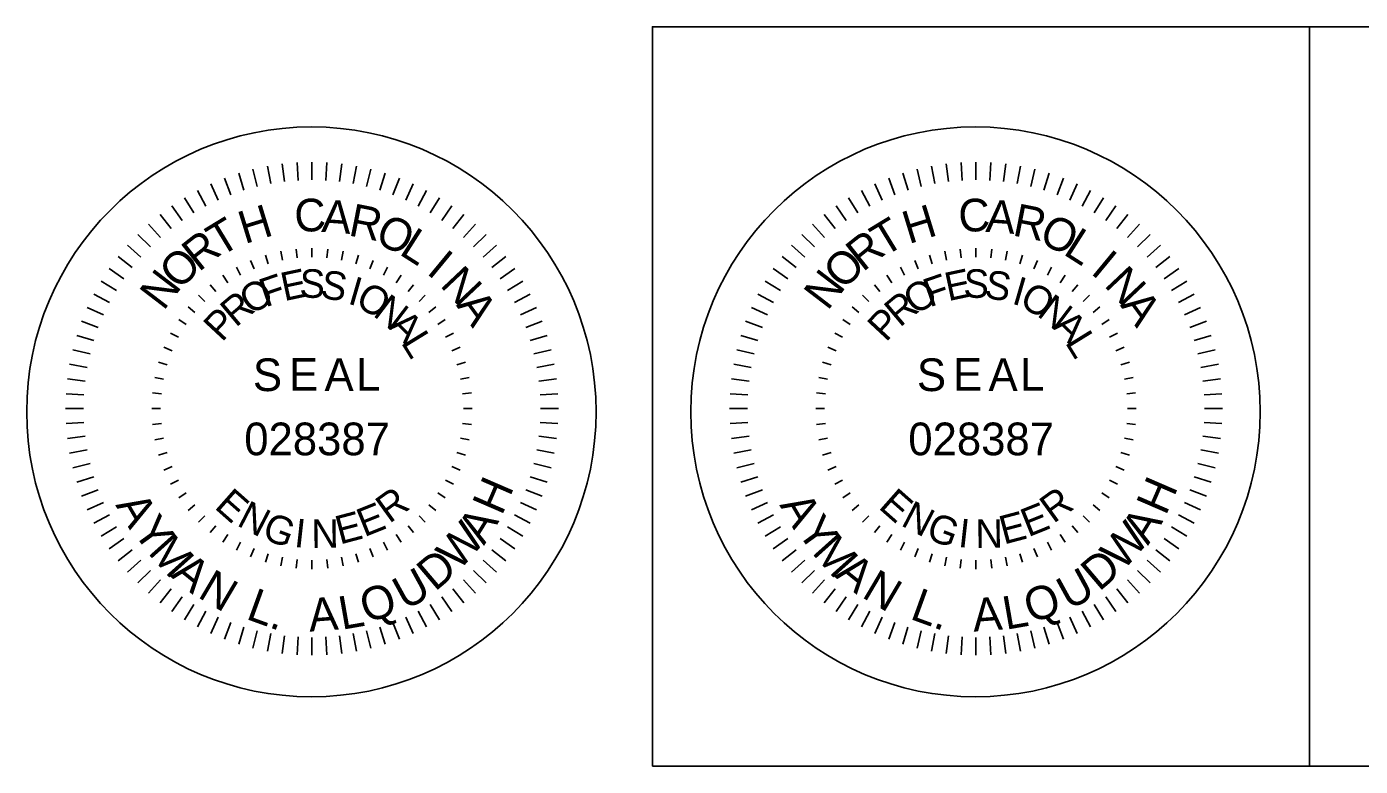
# Model space of a CAD drawing. Extents: x 1882804 to 1884487, y 844572 to 845443.
# Drawn here: x 1884074.3 to 1884277.3, y 845330.9 to 845443.4 of the extents above; entities that cross this region are included whole.
import ezdxf

# ---------------------------------------------------------------- set-up
doc = ezdxf.new("R2010")
doc.units = 0
doc.layers.add('Scratch_Level_1', color=7, linetype='Continuous')
doc.layers.add('Sheet Title CELL', color=7, linetype='Continuous')

msp = doc.modelspace()

# ---------------------------------------------------------------- linework, layer by layer
at = {"layer": 'Scratch_Level_1'}
for points in [[(1884169.55, 845330.93), (1884269.6, 845330.93), (1884269.6, 845443.43), (1884169.55, 845443.43)], [(1884269.6, 845330.93), (1884369.6, 845330.93), (1884369.6, 845443.43), (1884269.6, 845443.43)]]:
    msp.add_lwpolyline(points, close=True, dxfattribs=at)
for centre in [(1884117.65, 845384.84), (1884117.65, 845384.84), (1884218.73, 845384.84), (1884218.73, 845384.84)]:
    msp.add_circle(centre, 43.34, dxfattribs=at)
at = {"layer": 'Sheet Title CELL'}
for p, q in [((1884111.47, 845419.55), (1884110.98, 845422.21)), ((1884113.54, 845419.86), (1884113.22, 845422.55)), ((1884115.64, 845420.05), (1884115.47, 845422.76)), ((1884117.74, 845420.12), (1884117.74, 845422.83)), ((1884119.84, 845420.05), (1884120, 845422.76)), ((1884121.93, 845419.86), (1884122.26, 845422.55)), ((1884124.01, 845419.55), (1884124.5, 845422.21)), ((1884212.54, 845419.55), (1884212.05, 845422.21)), ((1884214.62, 845419.86), (1884214.29, 845422.55)), ((1884216.71, 845420.05), (1884216.55, 845422.76)), ((1884218.81, 845420.12), (1884218.81, 845422.83)), ((1884220.92, 845420.05), (1884221.08, 845422.76)), ((1884223.01, 845419.86), (1884223.34, 845422.55)), ((1884225.08, 845419.55), (1884225.57, 845422.21)), ((1884105.4, 845417.85), (1884104.44, 845420.39)), ((1884107.39, 845418.54), (1884106.58, 845421.13)), ((1884109.41, 845419.1), (1884108.76, 845421.74)), ((1884126.06, 845419.1), (1884126.71, 845421.74)), ((1884128.09, 845418.54), (1884128.89, 845421.13)), ((1884130.07, 845417.85), (1884131.04, 845420.39)), ((1884206.48, 845417.85), (1884205.52, 845420.39)), ((1884208.47, 845418.54), (1884207.66, 845421.13)), ((1884210.49, 845419.1), (1884209.84, 845421.74)), ((1884227.14, 845419.1), (1884227.79, 845421.74)), ((1884229.16, 845418.54), (1884229.97, 845421.13)), ((1884231.15, 845417.85), (1884232.11, 845420.39)), ((1884101.57, 845416.13), (1884100.31, 845418.53)), ((1884103.46, 845417.05), (1884102.35, 845419.52)), ((1884132.02, 845417.05), (1884133.13, 845419.52)), ((1884133.9, 845416.13), (1884135.16, 845418.53)), ((1884202.65, 845416.13), (1884201.39, 845418.53)), ((1884204.53, 845417.05), (1884203.42, 845419.52)), ((1884233.09, 845417.05), (1884234.2, 845419.52)), ((1884234.98, 845416.13), (1884236.24, 845418.53)), ((1884097.98, 845413.96), (1884096.43, 845416.19)), ((1884099.74, 845415.1), (1884098.34, 845417.42)), ((1884135.73, 845415.1), (1884137.14, 845417.42)), ((1884137.5, 845413.96), (1884139.04, 845416.19)), ((1884199.05, 845413.96), (1884197.51, 845416.19)), ((1884200.82, 845415.1), (1884199.41, 845417.42)), ((1884236.81, 845415.1), (1884238.21, 845417.42)), ((1884238.58, 845413.96), (1884240.12, 845416.19)), ((1884096.28, 845412.71), (1884094.61, 845414.84)), ((1884139.19, 845412.71), (1884140.86, 845414.84)), ((1884197.36, 845412.71), (1884195.69, 845414.84)), ((1884240.27, 845412.71), (1884241.94, 845414.84)), ((1884094.67, 845411.37), (1884092.87, 845413.4)), ((1884140.81, 845411.37), (1884142.61, 845413.4)), ((1884195.74, 845411.37), (1884193.95, 845413.4)), ((1884241.88, 845411.37), (1884243.68, 845413.4)), ((1884091.7, 845408.39), (1884089.67, 845410.19)), ((1884093.14, 845409.93), (1884091.22, 845411.84)), ((1884142.34, 845409.93), (1884144.25, 845411.84)), ((1884143.78, 845408.39), (1884145.81, 845410.19)), ((1884192.77, 845408.39), (1884190.75, 845410.19)), ((1884194.21, 845409.93), (1884192.3, 845411.84)), ((1884243.41, 845409.93), (1884245.33, 845411.84)), ((1884244.85, 845408.39), (1884246.88, 845410.19)), ((1884090.35, 845406.78), (1884088.22, 845408.45)), ((1884108.92, 845406.61), (1884108.4, 845407.87)), ((1884111.05, 845407.38), (1884110.65, 845408.67)), ((1884113.24, 845407.93), (1884112.98, 845409.26)), ((1884115.48, 845408.26), (1884115.35, 845409.61)), ((1884117.74, 845408.37), (1884117.74, 845409.72)), ((1884120, 845408.26), (1884120.13, 845409.61)), ((1884122.23, 845407.93), (1884122.5, 845409.26)), ((1884124.43, 845407.38), (1884124.82, 845408.67)), ((1884126.56, 845406.61), (1884127.07, 845407.87)), ((1884145.12, 845406.78), (1884147.26, 845408.45)), ((1884191.43, 845406.78), (1884189.29, 845408.45)), ((1884210, 845406.61), (1884209.48, 845407.87)), ((1884212.13, 845407.38), (1884211.73, 845408.67)), ((1884214.32, 845407.93), (1884214.05, 845409.26)), ((1884216.55, 845408.26), (1884216.42, 845409.61)), ((1884218.81, 845408.37), (1884218.81, 845409.72)), ((1884221.07, 845408.26), (1884221.2, 845409.61)), ((1884223.31, 845407.93), (1884223.58, 845409.26)), ((1884225.5, 845407.38), (1884225.9, 845408.67)), ((1884227.63, 845406.61), (1884228.15, 845407.87)), ((1884246.2, 845406.78), (1884248.34, 845408.45)), ((1884089.11, 845405.09), (1884086.88, 845406.63)), ((1884106.88, 845405.65), (1884106.24, 845406.84)), ((1884128.6, 845405.65), (1884129.24, 845406.84)), ((1884146.37, 845405.09), (1884148.6, 845406.63)), ((1884190.18, 845405.09), (1884187.95, 845406.63)), ((1884207.95, 845405.65), (1884207.31, 845406.84)), ((1884229.68, 845405.65), (1884230.31, 845406.84)), ((1884247.45, 845405.09), (1884249.68, 845406.63)), ((1884087.97, 845403.32), (1884085.64, 845404.73)), ((1884103.12, 845403.14), (1884102.26, 845404.18)), ((1884104.94, 845404.49), (1884104.18, 845405.61)), ((1884130.54, 845404.49), (1884131.29, 845405.61)), ((1884132.36, 845403.14), (1884133.21, 845404.18)), ((1884147.51, 845403.32), (1884149.83, 845404.73)), ((1884189.04, 845403.32), (1884186.72, 845404.73)), ((1884204.2, 845403.14), (1884203.34, 845404.18)), ((1884206.01, 845404.49), (1884205.26, 845405.61)), ((1884231.62, 845404.49), (1884232.37, 845405.61)), ((1884233.43, 845403.14), (1884234.29, 845404.18)), ((1884248.59, 845403.32), (1884250.91, 845404.73)), ((1884086.93, 845401.49), (1884084.53, 845402.75)), ((1884101.44, 845401.62), (1884100.49, 845402.58)), ((1884134.03, 845401.62), (1884134.99, 845402.58)), ((1884148.54, 845401.49), (1884150.94, 845402.75)), ((1884188.01, 845401.49), (1884185.61, 845402.75)), ((1884202.52, 845401.62), (1884201.56, 845402.58)), ((1884235.11, 845401.62), (1884236.07, 845402.58)), ((1884249.62, 845401.49), (1884252.02, 845402.75)), ((1884086.01, 845399.6), (1884083.54, 845400.72)), ((1884099.93, 845399.94), (1884098.88, 845400.8)), ((1884135.55, 845399.94), (1884136.6, 845400.8)), ((1884149.46, 845399.6), (1884151.93, 845400.72)), ((1884187.09, 845399.6), (1884184.62, 845400.72)), ((1884201, 845399.94), (1884199.95, 845400.8)), ((1884236.63, 845399.94), (1884237.67, 845400.8)), ((1884250.54, 845399.6), (1884253.01, 845400.72)), ((1884085.21, 845397.66), (1884082.67, 845398.62)), ((1884098.58, 845398.13), (1884097.45, 845398.88)), ((1884136.9, 845398.13), (1884138.02, 845398.88)), ((1884150.27, 845397.66), (1884152.8, 845398.62)), ((1884186.29, 845397.66), (1884183.75, 845398.62)), ((1884199.65, 845398.13), (1884198.53, 845398.88)), ((1884237.97, 845398.13), (1884239.1, 845398.88)), ((1884251.34, 845397.66), (1884253.88, 845398.62)), ((1884084.52, 845395.68), (1884081.94, 845396.48)), ((1884097.41, 845396.19), (1884096.22, 845396.83)), ((1884138.06, 845396.19), (1884139.26, 845396.83)), ((1884150.95, 845395.68), (1884153.54, 845396.48)), ((1884185.6, 845395.68), (1884183.01, 845396.48)), ((1884198.49, 845396.19), (1884197.3, 845396.83)), ((1884239.14, 845396.19), (1884240.33, 845396.83)), ((1884252.03, 845395.68), (1884254.62, 845396.48)), ((1884083.96, 845393.65), (1884081.33, 845394.3)), ((1884096.45, 845394.14), (1884095.2, 845394.66)), ((1884139.03, 845394.14), (1884140.28, 845394.66)), ((1884151.52, 845393.65), (1884154.15, 845394.3)), ((1884185.04, 845393.65), (1884182.4, 845394.3)), ((1884197.53, 845394.14), (1884196.27, 845394.66)), ((1884240.1, 845394.14), (1884241.36, 845394.66)), ((1884252.59, 845393.65), (1884255.23, 845394.3)), ((1884083.52, 845391.6), (1884080.85, 845392.08)), ((1884095.69, 845392.01), (1884094.39, 845392.41)), ((1884139.79, 845392.01), (1884141.09, 845392.41)), ((1884151.96, 845391.6), (1884154.62, 845392.08)), ((1884184.59, 845391.6), (1884181.93, 845392.08)), ((1884196.76, 845392.01), (1884195.47, 845392.41)), ((1884240.86, 845392.01), (1884242.16, 845392.41)), ((1884253.03, 845391.6), (1884255.7, 845392.08)), ((1884083.2, 845389.52), (1884080.51, 845389.85)), ((1884095.14, 845389.82), (1884093.81, 845390.08)), ((1884140.34, 845389.82), (1884141.67, 845390.08)), ((1884152.27, 845389.52), (1884154.96, 845389.85)), ((1884184.28, 845389.52), (1884181.59, 845389.85)), ((1884196.21, 845389.82), (1884194.89, 845390.08)), ((1884241.41, 845389.82), (1884242.74, 845390.08)), ((1884253.35, 845389.52), (1884256.04, 845389.85)), ((1884083.01, 845387.42), (1884080.31, 845387.59)), ((1884094.81, 845387.58), (1884093.46, 845387.72)), ((1884140.67, 845387.58), (1884142.02, 845387.72)), ((1884152.46, 845387.42), (1884155.17, 845387.59)), ((1884184.09, 845387.42), (1884181.38, 845387.59)), ((1884195.88, 845387.58), (1884194.53, 845387.72)), ((1884241.75, 845387.58), (1884243.09, 845387.72)), ((1884253.54, 845387.42), (1884256.25, 845387.59)), ((1884082.95, 845385.33), (1884080.24, 845385.33)), ((1884094.69, 845385.33), (1884093.34, 845385.33)), ((1884140.78, 845385.33), (1884142.13, 845385.33)), ((1884152.53, 845385.33), (1884155.24, 845385.33)), ((1884184.02, 845385.33), (1884181.31, 845385.33)), ((1884195.77, 845385.33), (1884194.42, 845385.33)), ((1884241.86, 845385.33), (1884243.21, 845385.33)), ((1884253.6, 845385.33), (1884256.31, 845385.33)), ((1884083.01, 845383.22), (1884080.31, 845383.06)), ((1884094.81, 845383.07), (1884093.46, 845382.94)), ((1884140.67, 845383.07), (1884142.02, 845382.94)), ((1884152.46, 845383.22), (1884155.17, 845383.06)), ((1884184.09, 845383.22), (1884181.38, 845383.06)), ((1884195.88, 845383.07), (1884194.53, 845382.94)), ((1884241.75, 845383.07), (1884243.09, 845382.94)), ((1884253.54, 845383.22), (1884256.25, 845383.06)), ((1884083.2, 845381.13), (1884080.51, 845380.81)), ((1884095.14, 845380.83), (1884093.81, 845380.57)), ((1884140.34, 845380.83), (1884141.67, 845380.57)), ((1884152.27, 845381.13), (1884154.96, 845380.81)), ((1884184.28, 845381.13), (1884181.59, 845380.81)), ((1884196.21, 845380.83), (1884194.88, 845380.57)), ((1884241.41, 845380.83), (1884242.74, 845380.57)), ((1884253.35, 845381.13), (1884256.04, 845380.81)), ((1884083.52, 845379.05), (1884080.85, 845378.57)), ((1884095.69, 845378.64), (1884094.39, 845378.24)), ((1884139.79, 845378.64), (1884141.09, 845378.24)), ((1884151.96, 845379.05), (1884154.62, 845378.57)), ((1884184.59, 845379.05), (1884181.93, 845378.57)), ((1884196.77, 845378.64), (1884195.47, 845378.24)), ((1884240.86, 845378.64), (1884242.16, 845378.24)), ((1884253.03, 845379.05), (1884255.7, 845378.57)), ((1884083.96, 845377), (1884081.33, 845376.35)), ((1884096.45, 845376.51), (1884095.2, 845375.99)), ((1884139.03, 845376.51), (1884140.28, 845375.99)), ((1884151.52, 845377), (1884154.15, 845376.35)), ((1884185.04, 845377), (1884182.4, 845376.35)), ((1884197.53, 845376.51), (1884196.27, 845375.99)), ((1884240.1, 845376.51), (1884241.36, 845375.99)), ((1884252.59, 845377), (1884255.23, 845376.35)), ((1884084.52, 845374.98), (1884081.94, 845374.17)), ((1884097.42, 845374.46), (1884096.22, 845373.82)), ((1884138.06, 845374.46), (1884139.26, 845373.82)), ((1884150.95, 845374.97), (1884153.54, 845374.17)), ((1884185.6, 845374.98), (1884183.01, 845374.17)), ((1884198.49, 845374.46), (1884197.3, 845373.82)), ((1884239.14, 845374.46), (1884240.33, 845373.82)), ((1884252.03, 845374.97), (1884254.61, 845374.17)), ((1884085.21, 845372.99), (1884082.67, 845372.03)), ((1884098.58, 845372.52), (1884097.45, 845371.77)), ((1884136.9, 845372.52), (1884138.02, 845371.77)), ((1884150.27, 845372.99), (1884152.8, 845372.03)), ((1884186.29, 845372.99), (1884183.75, 845372.03)), ((1884199.66, 845372.52), (1884198.53, 845371.77)), ((1884237.97, 845372.52), (1884239.1, 845371.77)), ((1884251.34, 845372.99), (1884253.88, 845372.03)), ((1884086.01, 845371.05), (1884083.54, 845369.93)), ((1884099.93, 845370.71), (1884098.88, 845369.85)), ((1884135.55, 845370.71), (1884136.6, 845369.85)), ((1884149.46, 845371.05), (1884151.93, 845369.93)), ((1884187.09, 845371.05), (1884184.62, 845369.93)), ((1884201, 845370.71), (1884199.95, 845369.85)), ((1884236.63, 845370.71), (1884237.67, 845369.85)), ((1884250.54, 845371.05), (1884253.01, 845369.93)), ((1884086.93, 845369.16), (1884084.53, 845367.9)), ((1884087.97, 845367.33), (1884085.64, 845365.92)), ((1884101.44, 845369.03), (1884100.49, 845368.07)), ((1884103.12, 845367.51), (1884102.26, 845366.47)), ((1884132.36, 845367.51), (1884133.21, 845366.47)), ((1884134.03, 845369.03), (1884134.99, 845368.07)), ((1884147.51, 845367.33), (1884149.83, 845365.92)), ((1884148.54, 845369.16), (1884150.94, 845367.9)), ((1884188.01, 845369.16), (1884185.61, 845367.9)), ((1884189.04, 845367.33), (1884186.72, 845365.92)), ((1884202.52, 845369.03), (1884201.56, 845368.07)), ((1884204.19, 845367.51), (1884203.34, 845366.47)), ((1884233.43, 845367.51), (1884234.29, 845366.47)), ((1884235.11, 845369.03), (1884236.07, 845368.07)), ((1884248.59, 845367.33), (1884250.91, 845365.92)), ((1884249.62, 845369.16), (1884252.02, 845367.9)), ((1884089.11, 845365.56), (1884086.88, 845364.02)), ((1884104.94, 845366.17), (1884104.18, 845365.04)), ((1884130.54, 845366.17), (1884131.29, 845365.04)), ((1884146.37, 845365.56), (1884148.6, 845364.02)), ((1884190.18, 845365.56), (1884187.95, 845364.02)), ((1884206.01, 845366.17), (1884205.26, 845365.04)), ((1884231.61, 845366.17), (1884232.37, 845365.04)), ((1884247.45, 845365.56), (1884249.68, 845364.02)), ((1884090.35, 845363.87), (1884088.22, 845362.2)), ((1884106.88, 845365), (1884106.24, 845363.81)), ((1884108.92, 845364.04), (1884108.4, 845362.79)), ((1884111.05, 845363.27), (1884110.65, 845361.98)), ((1884124.43, 845363.27), (1884124.82, 845361.98)), ((1884126.56, 845364.04), (1884127.07, 845362.79)), ((1884128.6, 845365), (1884129.24, 845363.81)), ((1884145.12, 845363.87), (1884147.26, 845362.2)), ((1884191.43, 845363.87), (1884189.29, 845362.2)), ((1884207.95, 845365), (1884207.31, 845363.81)), ((1884210, 845364.04), (1884209.48, 845362.79)), ((1884212.13, 845363.27), (1884211.73, 845361.98)), ((1884225.5, 845363.27), (1884225.9, 845361.98)), ((1884227.63, 845364.04), (1884228.15, 845362.79)), ((1884229.68, 845365), (1884230.31, 845363.81)), ((1884246.2, 845363.87), (1884248.34, 845362.2)), ((1884091.7, 845362.26), (1884089.67, 845360.46)), ((1884113.24, 845362.73), (1884112.98, 845361.4)), ((1884115.48, 845362.39), (1884115.35, 845361.05)), ((1884117.74, 845362.28), (1884117.74, 845360.93)), ((1884120, 845362.39), (1884120.13, 845361.05)), ((1884122.23, 845362.73), (1884122.5, 845361.4)), ((1884143.78, 845362.26), (1884145.81, 845360.46)), ((1884192.77, 845362.26), (1884190.75, 845360.46)), ((1884214.32, 845362.73), (1884214.05, 845361.4)), ((1884216.55, 845362.39), (1884216.42, 845361.05)), ((1884218.81, 845362.28), (1884218.81, 845360.93)), ((1884221.07, 845362.39), (1884221.2, 845361.05)), ((1884223.31, 845362.73), (1884223.58, 845361.4)), ((1884244.85, 845362.26), (1884246.88, 845360.46)), ((1884093.14, 845360.73), (1884091.22, 845358.81)), ((1884094.67, 845359.29), (1884092.87, 845357.26)), ((1884140.81, 845359.29), (1884142.61, 845357.26)), ((1884142.34, 845360.73), (1884144.25, 845358.81)), ((1884194.21, 845360.73), (1884192.3, 845358.81)), ((1884195.74, 845359.29), (1884193.95, 845357.26)), ((1884241.88, 845359.29), (1884243.68, 845357.26)), ((1884243.41, 845360.73), (1884245.33, 845358.81)), ((1884096.28, 845357.94), (1884094.61, 845355.81)), ((1884139.19, 845357.94), (1884140.87, 845355.81)), ((1884197.36, 845357.94), (1884195.69, 845355.81)), ((1884240.27, 845357.94), (1884241.94, 845355.81)), ((1884097.98, 845356.69), (1884096.43, 845354.46)), ((1884099.74, 845355.55), (1884098.34, 845353.23)), ((1884135.73, 845355.55), (1884137.14, 845353.23)), ((1884137.5, 845356.69), (1884139.04, 845354.46)), ((1884199.05, 845356.69), (1884197.51, 845354.46)), ((1884200.82, 845355.55), (1884199.41, 845353.23)), ((1884236.81, 845355.55), (1884238.21, 845353.23)), ((1884238.58, 845356.69), (1884240.12, 845354.46)), ((1884101.57, 845354.52), (1884100.31, 845352.12)), ((1884103.46, 845353.6), (1884102.35, 845351.13)), ((1884132.02, 845353.6), (1884133.13, 845351.13)), ((1884133.9, 845354.52), (1884135.16, 845352.12)), ((1884202.65, 845354.52), (1884201.39, 845352.12)), ((1884204.53, 845353.6), (1884203.42, 845351.13)), ((1884233.09, 845353.6), (1884234.2, 845351.13)), ((1884234.98, 845354.52), (1884236.24, 845352.12)), ((1884105.4, 845352.8), (1884104.44, 845350.26)), ((1884107.39, 845352.11), (1884106.58, 845349.52)), ((1884109.41, 845351.55), (1884108.76, 845348.92)), ((1884111.47, 845351.11), (1884110.98, 845348.44)), ((1884124.01, 845351.11), (1884124.5, 845348.44)), ((1884126.06, 845351.55), (1884126.71, 845348.92)), ((1884128.09, 845352.11), (1884128.89, 845349.52)), ((1884130.07, 845352.8), (1884131.04, 845350.26)), ((1884206.48, 845352.8), (1884205.52, 845350.26)), ((1884208.46, 845352.11), (1884207.66, 845349.52)), ((1884210.49, 845351.55), (1884209.84, 845348.92)), ((1884212.54, 845351.11), (1884212.05, 845348.44)), ((1884225.09, 845351.11), (1884225.57, 845348.44)), ((1884227.14, 845351.55), (1884227.79, 845348.92)), ((1884229.16, 845352.11), (1884229.97, 845349.52)), ((1884231.15, 845352.8), (1884232.11, 845350.26)), ((1884113.54, 845350.79), (1884113.22, 845348.1)), ((1884115.64, 845350.6), (1884115.47, 845347.89)), ((1884117.74, 845350.54), (1884117.74, 845347.83)), ((1884119.84, 845350.6), (1884120, 845347.89)), ((1884121.93, 845350.79), (1884122.26, 845348.1)), ((1884214.62, 845350.79), (1884214.29, 845348.1)), ((1884216.71, 845350.6), (1884216.55, 845347.89)), ((1884218.81, 845350.54), (1884218.81, 845347.83)), ((1884220.92, 845350.6), (1884221.08, 845347.89)), ((1884223.01, 845350.79), (1884223.33, 845348.1))]:
    msp.add_line(p, q, dxfattribs=at)

# ---------------------------------------------------------------- texts
for s, height, rotation, p in [('H', 4.97, 17.1424, (1884107.49, 845410.34)), ('C', 4.97, 2.9639, (1884115.18, 845412.16)), ('A', 4.97, 355.8747, (1884119.12, 845412.22)), ('R', 4.97, 348.7854, (1884123.15, 845411.7)), ('H', 4.97, 17.1424, (1884208.57, 845410.34)), ('C', 4.97, 2.9639, (1884216.26, 845412.16)), ('A', 4.97, 355.8747, (1884220.2, 845412.22)), ('R', 4.97, 348.7854, (1884224.23, 845411.7)), ('T', 4.97, 31.3208, (1884103.71, 845408.31)), ('O', 4.97, 334.607, (1884127.1, 845410.69)), ('T', 4.97, 31.3208, (1884204.79, 845408.31)), ('O', 4.97, 334.607, (1884228.17, 845410.69)), ('R', 4.97, 38.4101, (1884100.5, 845406.03)), ('L', 4.97, 327.5178, (1884130.85, 845408.9)), ('R', 4.97, 38.4101, (1884201.58, 845406.03)), ('L', 4.97, 327.5178, (1884231.93, 845408.9)), ('O', 4.97, 45.4993, (1884097.56, 845403.22)), ('I', 4.97, 320.4285, (1884135.03, 845405.97)), ('O', 4.97, 45.4993, (1884198.64, 845403.22)), ('I', 4.97, 320.4285, (1884236.11, 845405.97)), ('N', 4.97, 52.5885, (1884095.14, 845400.1)), ('F', 4.34, 18.9978, (1884110.65, 845400.71)), ('E', 4.34, 11.9657, (1884113.51, 845401.66)), ('S', 4.34, 357.9015, (1884115.78, 845402.26)), ('S', 4.34, 350.8693, (1884118.87, 845402.21)), ('N', 4.97, 313.3393, (1884137.09, 845404.05)), ('N', 4.97, 52.5885, (1884196.22, 845400.1)), ('F', 4.34, 18.9978, (1884211.73, 845400.71)), ('E', 4.34, 11.9657, (1884214.58, 845401.66)), ('S', 4.34, 357.9015, (1884216.85, 845402.26)), ('S', 4.34, 350.8693, (1884219.94, 845402.21)), ('N', 4.97, 313.3393, (1884238.17, 845404.05)), ('O', 4.34, 33.0621, (1884108.52, 845399.44)), ('I', 4.34, 343.8372, (1884123.03, 845401.34)), ('O', 4.34, 329.773, (1884124.13, 845401.11)), ('O', 4.34, 33.0621, (1884209.59, 845399.44)), ('I', 4.34, 343.8372, (1884224.11, 845401.34)), ('O', 4.34, 329.773, (1884225.2, 845401.11)), ('R', 4.34, 40.0942, (1884106.13, 845397.59)), ('N', 4.34, 322.7408, (1884126.87, 845399.55)), ('A', 4.97, 306.2501, (1884139.62, 845401.03)), ('R', 4.34, 40.0942, (1884207.21, 845397.59)), ('N', 4.34, 322.7408, (1884227.94, 845399.55)), ('A', 4.97, 306.2501, (1884240.69, 845401.03)), ('P', 4.34, 47.1263, (1884104.03, 845395.33)), ('P', 4.34, 47.1263, (1884205.1, 845395.33)), ('A', 4.34, 315.7087, (1884129.22, 845397.67)), ('A', 4.34, 315.7087, (1884230.3, 845397.67)), ('L', 4.34, 301.6445, (1884131.21, 845395.4)), ('L', 4.34, 301.6445, (1884232.29, 845395.4)), ('S', 4.97, 359.9999, (1884108.75, 845388)), ('E', 4.97, 359.9999, (1884114.26, 845388.05)), ('A', 4.97, 359.9999, (1884119.65, 845388.03)), ('L', 4.97, 359.9999, (1884124.46, 845388.05)), ('S', 4.97, 359.9999, (1884209.82, 845388)), ('E', 4.97, 359.9999, (1884215.33, 845388.05)), ('A', 4.97, 359.9999, (1884220.72, 845388.03)), ('L', 4.97, 359.9999, (1884225.53, 845388.05)), ('028387', 4.97, 359.9999, (1884107.43, 845378.24)), ('028387', 4.97, 359.9999, (1884208.51, 845378.24)), ('H', 5.05, 66.6238, (1884146.63, 845368.93)), ('H', 5.05, 66.6238, (1884247.7, 845368.93)), ('A', 5.05, 300.3517, (1884087.77, 845370.67)), ('E', 4.34, 318.5439, (1884102.74, 845370.27)), ('R', 4.34, 35.8972, (1884129.51, 845367.77)), ('A', 5.05, 300.3517, (1884188.85, 845370.67)), ('E', 4.34, 318.5439, (1884203.82, 845370.27)), ('R', 4.34, 35.8972, (1884230.59, 845367.77)), ('Y', 5.05, 305.796, (1884090.32, 845366.74)), ('N', 4.34, 332.6081, (1884106.14, 845367.63)), ('G', 4.34, 339.6402, (1884109.94, 845365.62)), ('E', 4.34, 14.8008, (1884121.98, 845364.64)), ('E', 4.34, 21.8329, (1884125.69, 845365.75)), ('A', 5.05, 58.2312, (1884143.92, 845364.43)), ('Y', 5.05, 305.796, (1884191.4, 845366.74)), ('N', 4.34, 332.6081, (1884207.22, 845367.63)), ('G', 4.34, 339.6402, (1884211.01, 845365.62)), ('E', 4.34, 14.8008, (1884223.05, 845364.64)), ('E', 4.34, 21.8329, (1884226.76, 845365.75)), ('A', 5.05, 58.2312, (1884244.99, 845364.43)), ('I', 4.34, 353.7045, (1884114.92, 845364.32)), ('N', 4.34, 0.7366, (1884117.66, 845364.13)), ('W', 5.05, 48.7814, (1884140.07, 845360.49)), ('I', 4.34, 353.7045, (1884215.99, 845364.32)), ('N', 4.34, 0.7366, (1884218.74, 845364.13)), ('W', 5.05, 48.7814, (1884241.15, 845360.49)), ('M', 5.05, 311.8424, (1884092.64, 845363.41)), ('M', 5.05, 311.8424, (1884193.71, 845363.41)), ('D', 5.05, 40.3887, (1884136.46, 845357.41)), ('D', 5.05, 40.3887, (1884237.54, 845357.41)), ('A', 5.05, 321.2643, (1884096.1, 845359.82)), ('U', 5.05, 28.768, (1884131.89, 845354.59)), ('A', 5.05, 321.2643, (1884197.17, 845359.82)), ('U', 5.05, 28.768, (1884232.97, 845354.59)), ('N', 5.05, 329.4227, (1884100.17, 845356.74)), ('N', 5.05, 329.4227, (1884201.25, 845356.74)), ('L.', 5.048, 340.0842, (1884107.53, 845353.4)), ('Q', 5.05, 18.4694, (1884126.06, 845352.63)), ('L.', 5.048, 340.0842, (1884208.6, 845353.4)), ('Q', 5.05, 18.4694, (1884227.14, 845352.63)), ('A', 5.05, 4.4131, (1884117.38, 845351.4)), ('L', 5.05, 9.9392, (1884122.28, 845351.68)), ('A', 5.05, 4.4131, (1884218.46, 845351.4)), ('L', 5.05, 9.9392, (1884223.35, 845351.68))]:
    msp.add_text(s, height=height, rotation=rotation, dxfattribs=at).set_placement(p)

doc.saveas('drawing.dxf')
